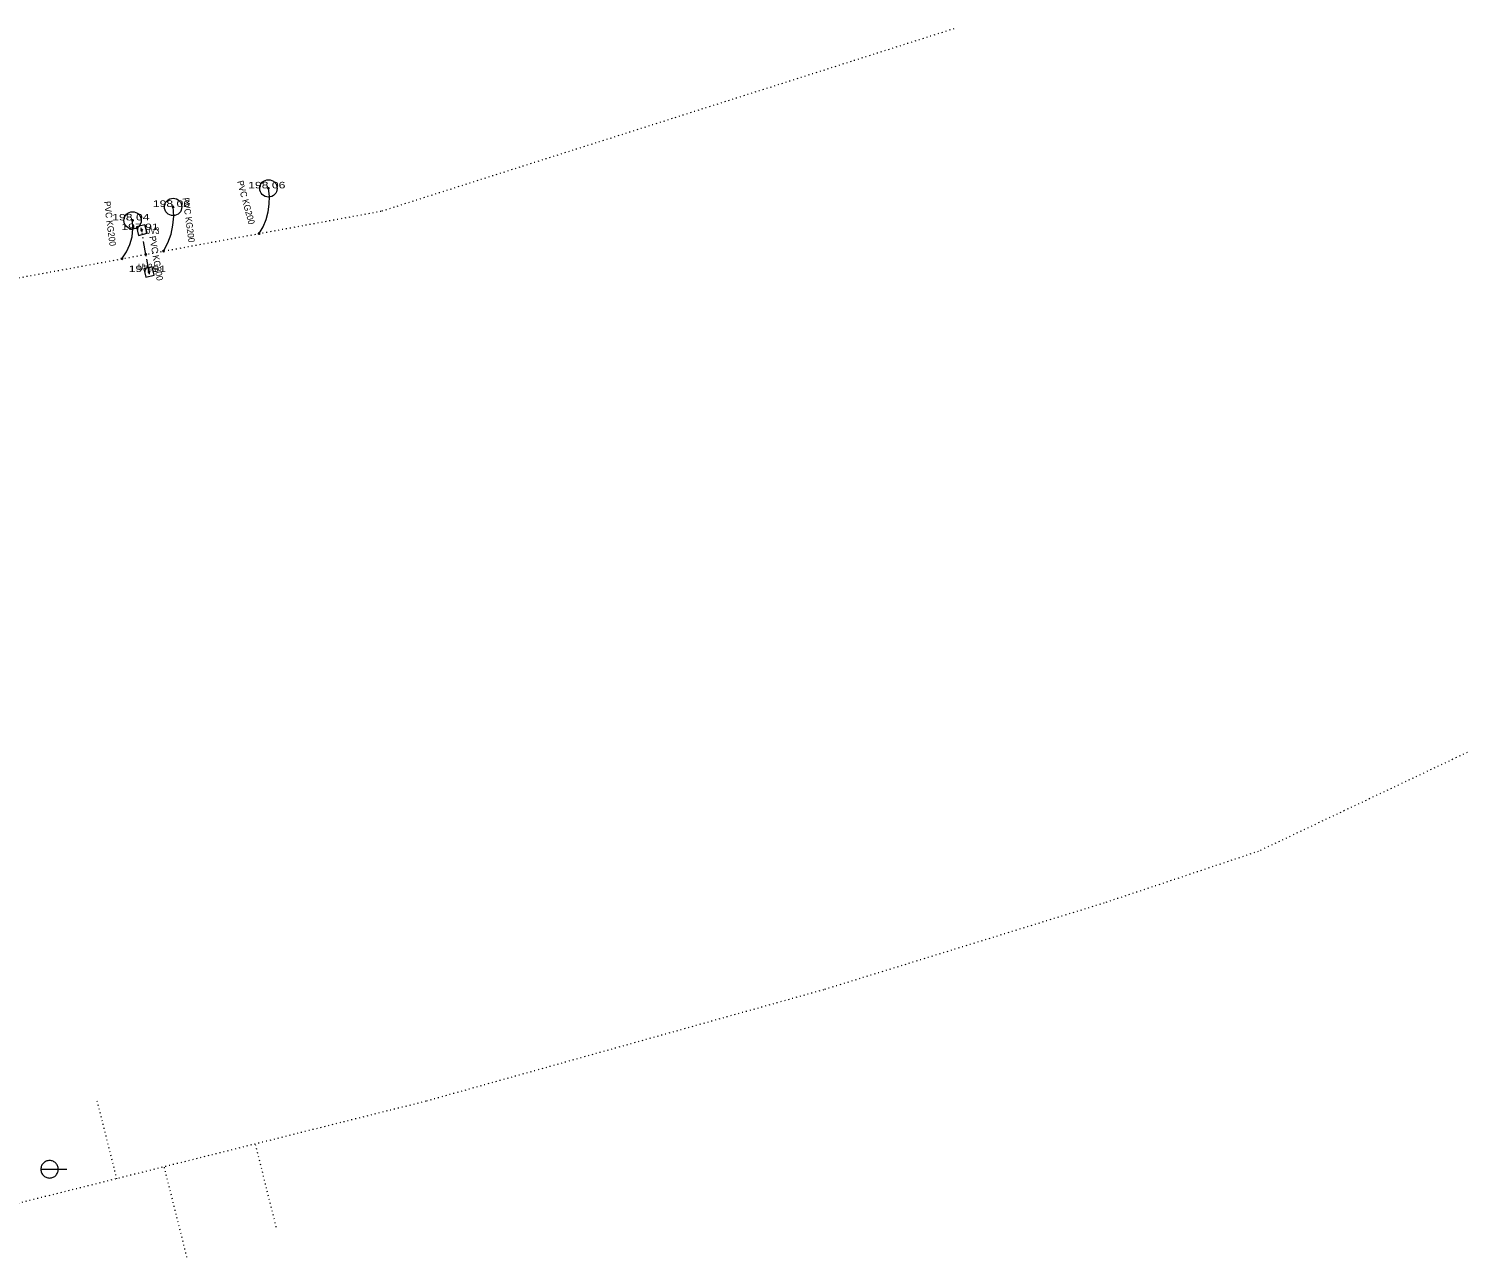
# Model space of a CAD drawing. Extents: x -688177 to -687620, y -1056713 to -1056287.
# Drawn here: x -687785.1 to -687619.5, y -1056670.4 to -1056529.1 of the extents above; entities that cross this region are included whole.
import ezdxf
from ezdxf.enums import TextEntityAlignment as Align

# ---------------------------------------------------------------- set-up
doc = ezdxf.new("R2010")
doc.units = 0
doc.header["$LTSCALE"] = 0.3
doc.header["$PDMODE"] = 32
doc.header["$PDSIZE"] = 0.15
for name, pattern in [('DASH_DOUBLE_DOT', [9.2, 5, -1.2, 0.3, -1.2, 0.3, -1.2]), ('DOTTED', [1.5, 0.3, -1.2]), ('LONG_DASHED', [7.5, 6, -1.5])]:
    doc.linetypes.add(name, pattern=pattern)
for name, color, linetype in [('1', 7, 'Continuous'), ('19', 7, 'Continuous'), ('3', 7, 'Continuous')]:
    doc.layers.add(name, color=color, linetype=linetype)
for name, color, linetype, lineweight in [('10', 7, 'Continuous', 13), ('12', 7, 'Continuous', 13), ('46', 7, 'DOTTED', 13), ('50', 7, 'LONG_DASHED', 13), ('51', 7, 'DASH_DOUBLE_DOT', 13)]:
    doc.layers.add(name, color=color, linetype=linetype, lineweight=lineweight)

msp = doc.modelspace()

# ---------------------------------------------------------------- linework, layer by layer
at = {"layer": '1'}
for p in [(-687757.47, -1056547.41), (-687768.44, -1056549.54), (-687773.11, -1056551.1), (-687772.06, -1056552.21), (-687758.55, -1056552.61), (-687771.58, -1056555.01), (-687769.54, -1056554.63), (-687774.33, -1056555.51), (-687771.21, -1056557.04)]:
    msp.add_point(p, dxfattribs=at)
at = {"layer": '10'}
for p, q in [((-687771.996, -1056552.452), (-687772.124, -1056551.968)), ((-687771.152, -1056557.283), (-687771.268, -1056556.797))]:
    msp.add_line(p, q, dxfattribs=at)
for points in [[(-687771.449, -1056552.567), (-687771.703, -1056551.599), (-687772.671, -1056551.853), (-687772.417, -1056552.821)], [(-687770.607, -1056557.41), (-687770.84, -1056556.437), (-687771.813, -1056556.67), (-687771.58, -1056557.643)]]:
    msp.add_lwpolyline(points, close=True, dxfattribs=at)
for centre in [(-687757.47, -1056547.41), (-687768.44, -1056549.54), (-687773.11, -1056551.1)]:
    msp.add_circle(centre, 1, dxfattribs=at)
at = {"layer": '12'}
msp.add_line((-687783.668, -1056660.26), (-687780.692, -1056660.26), dxfattribs=at)
msp.add_lwpolyline([(-687782.66, -1056659.252), (-687782.765, -1056659.258), (-687782.869, -1056659.274), (-687782.971, -1056659.302), (-687783.07, -1056659.34), (-687783.164, -1056659.387), (-687783.252, -1056659.445), (-687783.334, -1056659.511), (-687783.409, -1056659.586), (-687783.475, -1056659.668), (-687783.533, -1056659.756), (-687783.58, -1056659.85), (-687783.618, -1056659.949), (-687783.646, -1056660.051), (-687783.662, -1056660.155), (-687783.668, -1056660.26), (-687783.662, -1056660.365), (-687783.646, -1056660.47), (-687783.618, -1056660.572), (-687783.58, -1056660.67), (-687783.533, -1056660.764), (-687783.475, -1056660.853), (-687783.409, -1056660.935), (-687783.334, -1056661.009), (-687783.252, -1056661.075), (-687783.164, -1056661.133), (-687783.07, -1056661.181), (-687782.971, -1056661.219), (-687782.869, -1056661.246), (-687782.765, -1056661.262), (-687782.66, -1056661.268), (-687782.555, -1056661.262), (-687782.45, -1056661.246), (-687782.348, -1056661.219), (-687782.25, -1056661.181), (-687782.156, -1056661.133), (-687782.067, -1056661.075), (-687781.985, -1056661.009), (-687781.911, -1056660.935), (-687781.845, -1056660.853), (-687781.787, -1056660.764), (-687781.739, -1056660.67), (-687781.701, -1056660.572), (-687781.674, -1056660.47), (-687781.658, -1056660.365), (-687781.652, -1056660.26), (-687781.658, -1056660.155), (-687781.674, -1056660.051), (-687781.701, -1056659.949), (-687781.739, -1056659.85), (-687781.787, -1056659.756), (-687781.845, -1056659.668), (-687781.911, -1056659.586), (-687781.985, -1056659.511), (-687782.067, -1056659.445), (-687782.156, -1056659.387), (-687782.25, -1056659.34), (-687782.348, -1056659.302), (-687782.45, -1056659.274), (-687782.555, -1056659.258)], close=True, dxfattribs=at)
at = {"layer": '46'}
for points in [[(-687678.6, -1056529.05), (-687744.5, -1056550.06), (-687838.03, -1056567.26)], [(-687619.52, -1056612.31), (-687643.56, -1056623.69), (-687661.29, -1056629.63), (-687693.58, -1056639.61), (-687739.36, -1056652.44), (-687788.41, -1056664.72)]]:
    msp.add_lwpolyline(points, dxfattribs=at)
at = {"layer": '50', "linetype": 'DASH_DOUBLE_DOT'}
for points in [[(-687758.548, -1056552.608), (-687758.096, -1056551.823), (-687757.747, -1056550.987), (-687757.507, -1056550.113), (-687757.38, -1056549.216), (-687757.367, -1056548.31), (-687757.47, -1056547.41)], [(-687769.538, -1056554.629), (-687769.045, -1056553.69), (-687768.684, -1056552.693), (-687768.46, -1056551.656), (-687768.378, -1056550.599), (-687768.44, -1056549.54)], [(-687774.332, -1056555.511), (-687773.81, -1056554.73), (-687773.418, -1056553.877), (-687773.167, -1056552.972), (-687773.064, -1056552.038), (-687773.11, -1056551.1)], [(-687771.21, -1056557.04), (-687771.584, -1056555.005), (-687772.06, -1056552.21)]]:
    msp.add_lwpolyline(points, dxfattribs=at)
at = {"layer": '51', "linetype": 'DOTTED'}
for p, q in [((-687777.21, -1056652.37), (-687774.96, -1056661.35)), ((-687756.57, -1056666.91), (-687758.97, -1056657.35)), ((-687766.86, -1056670.38), (-687769.46, -1056659.98))]:
    msp.add_line(p, q, dxfattribs=at)

# ---------------------------------------------------------------- texts
at = {"layer": '19', "width": 0.95}
for rotation, p in [(285.199, (-687761.101, -1056546.627)), (277.456, (-687767.348, -1056548.529)), (277.456, (-687776.419, -1056548.936)), (279.661, (-687771.189, -1056552.96))]:
    msp.add_text('PVC KG200', height=0.75, rotation=rotation, dxfattribs=at).set_placement(p)
at = {"layer": '19', "width": 0.85}
for s, p in [('UV3', (-687771.67, -1056552.66)), ('UV2', (-687772.49, -1056556.83))]:
    msp.add_text(s, height=0.75, dxfattribs=at).set_placement(p)
at = {"layer": '3', "width": 1.4}
for s, p in [('198 06 ', (-687757.47, -1056547.41)), ('198 06 ', (-687768.44, -1056549.54)), ('198 04 ', (-687773.11, -1056551.1)), ('197 91 ', (-687772.06, -1056552.21)), ('197 91 ', (-687771.21, -1056557.04))]:
    msp.add_text(s, height=0.75, dxfattribs=at).set_placement(p, align=Align.CENTER)

doc.saveas('drawing.dxf')
